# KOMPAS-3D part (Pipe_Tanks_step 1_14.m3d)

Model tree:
1. X Axis
2. Y Axis
3. Z Axis  (labels: Bend 90 Dn 50; Pipe Dn 50; C:\Program Files\ASCON\KOMPAS-3D V10\Sys\graphic.lyt; Pipe_Tanks_step 1_14.m3d)
     Òîëùèíà ñòåíêè 1 = 1

Referenced files in C:\Documents and Settings\kashirsky\Мои документы\Camtasia Studio\Pipelines3D\Tanks\: Tanks_step 1.a3d, Tanks_step 1.spw
Referenced files in C:\Documents and Settings\kashirsky\Мои документы\Camtasia Studio\Pipelines3D\Tanks\Tanks_step 1_Pipes\: Pipe_Tanks_step 1_14.m3d
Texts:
  Pipe Dn 50
  Steel ASTM A295
  Three Point Plane
  Plane at Angle
  Line and Point Plane
  Axis through Two Vertices
  Axis of Feature
  Axis of Conical Surface
  Axis through Edge
  Trim by Surface
  Trim by Sketch
  Feature with No History
  Intersection Axis of Two Planes
  Two Line Plane
  Line and Face Plane
  Bend by line
  Hole in sheet body
  Cut in sheet body
  Point in CM
  Linear Dimension from Line to Point
  Surface Finish Symbol
  Geometric Tolerance Symbol
  Leader #1
  Leader #2
  Leader #3
  Shape Deviations and Datum
  Node point number
  Mark of coordination axis
  Node point designation
  Mark/Reference designation with leader
  Mark/reference designation on line
  Mark/Reference designation without leader
  Bend 90 Dn 50
  Plane of section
